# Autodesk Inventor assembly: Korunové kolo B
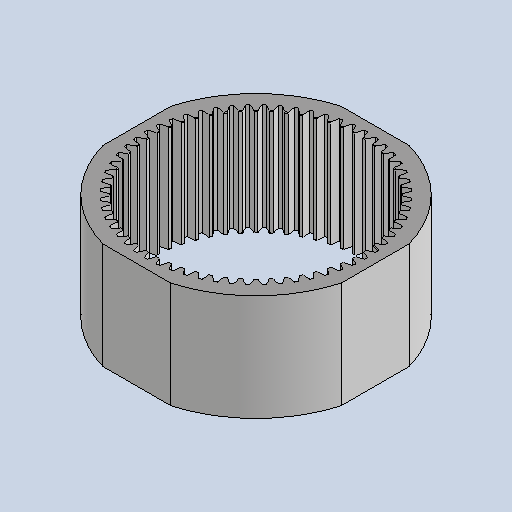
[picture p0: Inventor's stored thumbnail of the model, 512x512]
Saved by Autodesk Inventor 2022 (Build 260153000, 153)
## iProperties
Created: 2025-05
Part Number: Korunové kolo B
Document SubType Name: Assembly
Designer: jbart
Mass: 5966.28 g
Surface Area: 6901.86 cm^2
Volume: 5966.28 cm^3
Density: 1 g/cm^3
Author: jbart
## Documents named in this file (2)
- C:\Users\jbart\OneDrive\Dokumenty\Inventor\Převodovka navijáku\Korunové kolo 2.iam
- C:\Users\jbart\OneDrive\Dokumenty\Inventor\Převodovka navijáku\Korunové kolo 2\Design Accelerator\Čelní ozubená kola1.iam
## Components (1 placed, 1 different names)
1. Čelní ozubená kola:1 [sub-assembly]
